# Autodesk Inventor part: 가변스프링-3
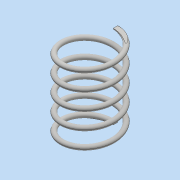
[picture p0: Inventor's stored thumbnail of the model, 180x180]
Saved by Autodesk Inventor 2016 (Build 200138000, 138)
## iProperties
Created: 2015-11
Part Number: 가변스프링-3
Material: 일반
Document SubType Name: Modeling
Designer: Administrator
Density: 1 g/cm^3
Appearance: 기본값
Mass: 1.06136 g
Surface Area: 21.6655 cm^2
Volume: 1.06136 cm^3
Author: Administrator
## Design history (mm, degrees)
sketch "스케치2"
  geometry: L1 (0, 0)-(11, 0); L2 (11, 0)-(11, 29.193); L3 (11, 29.193)-(0, 29.193); L4 (0, 29.193)-(0, 0); C1 r 1 at (11, 0)
  constraints: 8 end point, 2 parallel, 1 centre point, 1 coincident, 1 horizontal, 1 perpendicular
  dimensions: "d0" = 2 diameter of C1; "d1" = 22 diameter of L2 L4; "d2" = 29.19259 distance between parallel lines of L3 L1 (derived)
feature "코일1" sketch "스케치2" pitch "d3" = 10; turns "d5" = 5; dims "d4" = 29.19259 (= d2), "d6" = 0, angle "d7" = 90 deg, angle "d8" = 90 deg, "d9" = 0, "d10" = 0
sketch "스케치3"
  geometry: L1 (0, 12)-(0, 10) reference; 1 further point
  constraints: 1 vertical alignment
extrude "돌출1" cut sketch "스케치3" distance "d11" = 10; taper "d12" = 0 deg
node "작업 평면1"
sketch "스케치4"
  geometry: L1 (0, -1)-(0, 1) reference; 1 further point
  constraints: 1 vertical alignment
extrude "돌출2" cut sketch "스케치4" distance "d13" = 10; taper "d14" = 0 deg
node "솔리드1"
node "절단 모서리 투영1"
node "절단 모서리 투영2"
